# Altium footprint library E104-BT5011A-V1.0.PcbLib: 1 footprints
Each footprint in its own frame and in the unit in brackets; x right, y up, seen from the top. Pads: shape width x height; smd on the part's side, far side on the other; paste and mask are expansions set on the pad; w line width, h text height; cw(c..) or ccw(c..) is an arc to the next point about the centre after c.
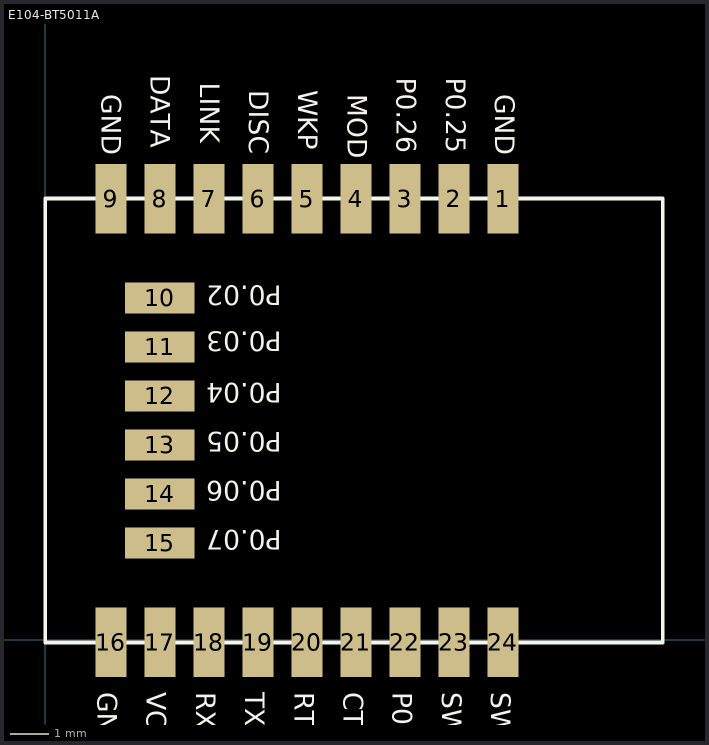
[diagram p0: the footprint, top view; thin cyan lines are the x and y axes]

## E104-BT5011A [mm]
pads (24):
  rect 0.8x1.8 smd: 1(11.86,11.43) 2(10.59,11.43) 3(9.32,11.43) 4(8.05,11.43) 5(6.78,11.43) 6(5.51,11.43) 7(4.24,11.43) 8(2.97,11.43) 9(1.7,11.43) 16(1.7,-0.07) 17(2.97,-0.07) 18(4.24,-0.07) 19(5.51,-0.07) 20(6.78,-0.07) 21(8.05,-0.07) 22(9.32,-0.07) 23(10.59,-0.07) 24(11.86,-0.07)
  rect 1.8x0.8 smd: 10(2.97,8.855) 11(2.97,7.585) 12(2.97,6.315) 13(2.97,5.045) 14(2.97,3.775) 15(2.97,2.505)
Top Overlay:
  lines w0.1: 0,-0.07 16,-0.07 16,11.43 0,11.43 0,-0.07
  text "GND" at 11.66,14.139 h0.5
  text "P0.25" at 10.385,14.567 h0.5
  text "P0.26" at 9.11,14.567 h0.5
  text "MOD" at 7.835,14.139 h0.5
  text "WKP" at 6.56,14.242 h0.5
  text "DISC" at 5.285,14.236 h0.5
  text "LINK" at 4.01,14.427 h0.5
  text "DATA" at 2.735,14.63 h0.5
  text "VCC" at 2.635,-1.361 h0.5
  text "RXD" at 3.91,-1.361 h0.5
  text "TXD" at 5.185,-1.361 h0.5
  text "RTS" at 6.46,-1.361 h0.5
  text "CTS" at 7.735,-1.361 h0.5
  text "P0.21/RST" at 9.01,-1.361 h0.5
  text "SWDCLK" at 10.285,-1.361 h0.5
  text "SWDIO" at 11.56,-1.361 h0.5
  text "P0.07" at 6.123,2.835 h0.5
  text "P0.05" at 6.123,5.375 h0.5
  text "P0.04" at 6.123,6.645 h0.5
  text "P0.02" at 6.123,9.174 h0.5
  text "P0.06" at 6.123,4.105 h0.5
  text "P0.03" at 6.123,7.976 h0.5
  text "GND" at 1.46,14.139 h0.5
  text "GND" at 1.36,-1.361 h0.5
